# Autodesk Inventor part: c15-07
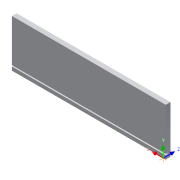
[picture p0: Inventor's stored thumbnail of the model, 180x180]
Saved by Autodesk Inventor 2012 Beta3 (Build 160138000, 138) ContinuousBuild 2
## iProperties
Created: 2011-02
Part Number: c15-07
Material: Default
Document SubType Name: Modeling
Designer: Beta-8540w
Density: 1 g/cm^3
Author: Beta-8540w
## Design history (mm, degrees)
derived "c15-06.ipt"
  node "UCS1: X Axis"
  node "UCS1: Y Axis"
  node "UCS1: Z Axis"
node "UCS1" dims "d1" = 6.35, "d2" = 0, "d3" = 0, "d4" = 0, "d5" = 0, "d6" = 0
feature "Solid1::c15-06.ipt" dims "d0" = 10
tag "TaggingFeature1"
body "Solid1"
node "UCS1: YZ Plane"
node "UCS1: XZ Plane"
node "UCS1: XY Plane"
node "UCS1: Center Point"
